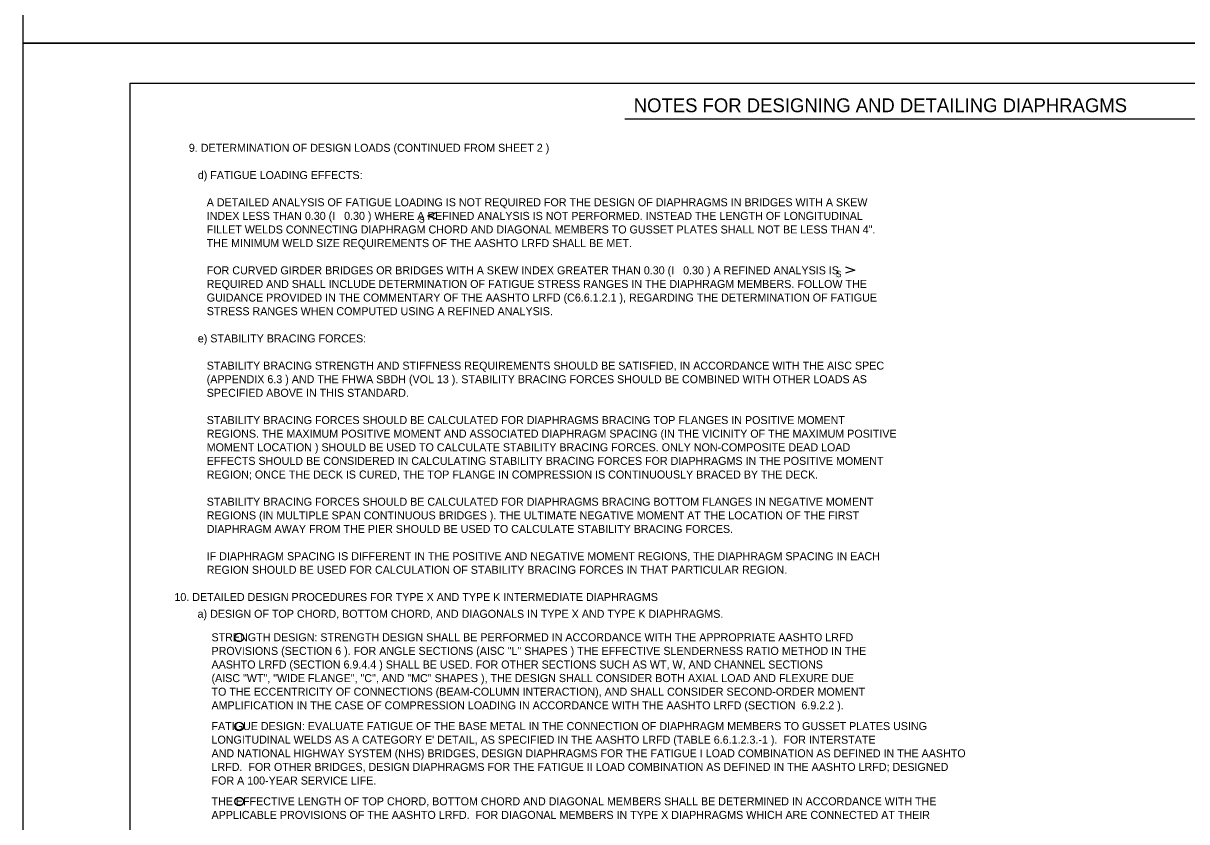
# Model space of a CAD drawing. Extents: x 634656 to 641360, y 298715 to 301183.
# Drawn here: x 637375.4 to 637811.5, y 299027.4 to 299326.5 of the extents above; entities that cross this region are included whole.
import ezdxf

# ---------------------------------------------------------------- set-up
doc = ezdxf.new("R2010")
doc.units = 0
for name, color, linetype in [('1', 7, 'Continuous'), ('2', 7, 'Continuous'), ('PLT-BNDY', 7, 'Continuous')]:
    doc.layers.add(name, color=color, linetype=linetype)

msp = doc.modelspace()

# ---------------------------------------------------------------- linework, layer by layer
at = {"layer": '1'}
for points in [[(637530.45, 299255.59), (637526.91, 299254.41), (637530.45, 299253.23)], [(637683.57, 299235.19), (637687.11, 299234.01), (637683.57, 299232.83)]]:
    msp.add_lwpolyline(points, dxfattribs=at)
for centre in [(637456.32, 299096.41), (637456.32, 299063.06), (637456.32, 299034.89)]:
    msp.add_circle(centre, 1.61, dxfattribs=at)
at = {"layer": '2'}
for p, q in [((637415.43, 298739.99), (637415.43, 299303.99)), ((637415.43, 299303.99), (638201.43, 299303.99)), ((637600.92, 299290.65), (637946.3, 299290.65))]:
    msp.add_line(p, q, dxfattribs=at)
at = {"layer": 'PLT-BNDY'}
for points in [[(637375.43, 299912.99), (638216.43, 299912.99), (638216.43, 299318.99), (637375.43, 299318.99)], [(637375.43, 299318.99), (638216.43, 299318.99), (638216.43, 298724.99), (637375.43, 298724.99)]]:
    msp.add_lwpolyline(points, close=True, dxfattribs=at)

# ---------------------------------------------------------------- texts
at = {"layer": '1'}
for s, height, p in [('NOTES FOR DESIGNING AND DETAILING DIAPHRAGMS ', 5.1838, (637604.21, 299293.18)), ('9. DETERMINATION OF DESIGN LOADS (CONTINUED FROM SHEET 2 )', 2.9999, (637437.49, 299278.33)), ('   d) FATIGUE LOADING EFFECTS:', 2.9999, (637437.49, 299268.13)), ('      A DETAILED ANALYSIS OF FATIGUE LOADING IS NOT REQUIRED FOR THE DESIGN OF DIAPHRAGMS IN BRIDGES WITH A SKEW', 2.99987, (637437.49, 299257.93)), ('      INDEX LESS THAN 0.30 (I   0.30 ) WHERE A REFINED ANALYSIS IS NOT PERFORMED. INSTEAD THE LENGTH OF LONGITUDINAL', 2.99987, (637437.49, 299252.83)), ('      FILLET WELDS CONNECTING DIAPHRAGM CHORD AND DIAGONAL MEMBERS TO GUSSET PLATES SHALL NOT BE LESS THAN 4".', 2.99987, (637437.49, 299247.73)), ('S', 2.4, (637523.72, 299251.78)), ('      THE MINIMUM WELD SIZE REQUIREMENTS OF THE AASHTO LRFD SHALL BE MET.', 2.9999, (637437.49, 299242.63)), ('      FOR CURVED GIRDER BRIDGES OR BRIDGES WITH A SKEW INDEX GREATER THAN 0.30 (I   0.30 ) A REFINED ANALYSIS IS', 2.99987, (637437.49, 299232.43)), ('S', 2.4, (637679.92, 299231.38)), ('      REQUIRED AND SHALL INCLUDE DETERMINATION OF FATIGUE STRESS RANGES IN THE DIAPHRAGM MEMBERS. FOLLOW THE', 2.99987, (637437.49, 299227.33)), ('      GUIDANCE PROVIDED IN THE COMMENTARY OF THE AASHTO LRFD (C6.6.1.2.1 ), REGARDING THE DETERMINATION OF FATIGUE', 2.99987, (637437.49, 299222.23)), ('      STRESS RANGES WHEN COMPUTED USING A REFINED ANALYSIS.', 2.9999, (637437.49, 299217.13)), ('   e) STABILITY BRACING FORCES:', 2.9999, (637437.49, 299206.93)), ('      STABILITY BRACING STRENGTH AND STIFFNESS REQUIREMENTS SHOULD BE SATISFIED, IN ACCORDANCE WITH THE AISC SPEC', 2.99987, (637437.49, 299196.73)), ('      (APPENDIX 6.3 ) AND THE FHWA SBDH (VOL 13 ). STABILITY BRACING FORCES SHOULD BE COMBINED WITH OTHER LOADS AS', 2.99987, (637437.49, 299191.64)), ('      SPECIFIED ABOVE IN THIS STANDARD.', 2.9999, (637437.49, 299186.54)), ('      STABILITY BRACING FORCES SHOULD BE CALCULATED FOR DIAPHRAGMS BRACING TOP FLANGES IN POSITIVE MOMENT', 2.99987, (637437.49, 299176.34)), ('      REGIONS. THE MAXIMUM POSITIVE MOMENT AND ASSOCIATED DIAPHRAGM SPACING (IN THE VICINITY OF THE MAXIMUM POSITIVE', 2.99987, (637437.49, 299171.24)), ('      MOMENT LOCATION ) SHOULD BE USED TO CALCULATE STABILITY BRACING FORCES. ONLY NON-COMPOSITE DEAD LOAD', 2.99987, (637437.49, 299166.14)), ('      EFFECTS SHOULD BE CONSIDERED IN CALCULATING STABILITY BRACING FORCES FOR DIAPHRAGMS IN THE POSITIVE MOMENT', 2.99987, (637437.49, 299161.04)), ('      REGION; ONCE THE DECK IS CURED, THE TOP FLANGE IN COMPRESSION IS CONTINUOUSLY BRACED BY THE DECK.', 2.99987, (637437.49, 299155.94)), ('      STABILITY BRACING FORCES SHOULD BE CALCULATED FOR DIAPHRAGMS BRACING BOTTOM FLANGES IN NEGATIVE MOMENT', 2.99987, (637437.49, 299145.74)), ('      REGIONS (IN MULTIPLE SPAN CONTINUOUS BRIDGES ). THE ULTIMATE NEGATIVE MOMENT AT THE LOCATION OF THE FIRST', 2.99987, (637437.49, 299140.64)), ('      DIAPHRAGM AWAY FROM THE PIER SHOULD BE USED TO CALCULATE STABILITY BRACING FORCES.', 2.9999, (637437.49, 299135.54)), ('      IF DIAPHRAGM SPACING IS DIFFERENT IN THE POSITIVE AND NEGATIVE MOMENT REGIONS, THE DIAPHRAGM SPACING IN EACH', 2.99987, (637437.49, 299125.34)), ('      REGION SHOULD BE USED FOR CALCULATION OF STABILITY BRACING FORCES IN THAT PARTICULAR REGION.', 2.9999, (637437.49, 299120.24)), ('10. DETAILED DESIGN PROCEDURES FOR TYPE X AND TYPE K INTERMEDIATE DIAPHRAGMS', 2.9999, (637432.07, 299110.04)), ('   a) DESIGN OF TOP CHORD, BOTTOM CHORD, AND DIAGONALS IN TYPE X AND TYPE K DIAPHRAGMS. ', 2.9999, (637437.42, 299103.75)), ('        STRENGTH DESIGN: STRENGTH DESIGN SHALL BE PERFORMED IN ACCORDANCE WITH THE APPROPRIATE AASHTO LRFD', 2.99987, (637437.06, 299094.96)), ('        PROVISIONS (SECTION 6 ). FOR ANGLE SECTIONS (AISC "L" SHAPES ) THE EFFECTIVE SLENDERNESS RATIO METHOD IN THE', 2.99987, (637437.06, 299089.86)), ('        AASHTO LRFD (SECTION 6.9.4.4 ) SHALL BE USED. FOR OTHER SECTIONS SUCH AS WT, W, AND CHANNEL SECTIONS ', 2.99987, (637437.06, 299084.76)), ('        (AISC "WT", "WIDE FLANGE", "C", AND "MC" SHAPES ), THE DESIGN SHALL CONSIDER BOTH AXIAL LOAD AND FLEXURE DUE ', 2.99987, (637437.06, 299079.67)), ('        TO THE ECCENTRICITY OF CONNECTIONS (BEAM-COLUMN INTERACTION), AND SHALL CONSIDER SECOND-ORDER MOMENT ', 2.99987, (637437.06, 299074.57)), ('        AMPLIFICATION IN THE CASE OF COMPRESSION LOADING IN ACCORDANCE WITH THE AASHTO LRFD (SECTION  6.9.2.2 ).', 2.99987, (637437.06, 299069.47)), ('        FATIGUE DESIGN: EVALUATE FATIGUE OF THE BASE METAL IN THE CONNECTION OF DIAPHRAGM MEMBERS TO GUSSET PLATES USING', 2.99987, (637437.06, 299061.69)), ("        LONGITUDINAL WELDS AS A CATEGORY E' DETAIL, AS SPECIFIED IN THE AASHTO LRFD (TABLE 6.6.1.2.3.-1 ).  FOR INTERSTATE", 2.99987, (637437.06, 299056.59)), ('        AND NATIONAL HIGHWAY SYSTEM (NHS) BRIDGES, DESIGN DIAPHRAGMS FOR THE FATIGUE I LOAD COMBINATION AS DEFINED IN THE AASHTO', 2.99987, (637437.06, 299051.49)), ('        LRFD.  FOR OTHER BRIDGES, DESIGN DIAPHRAGMS FOR THE FATIGUE II LOAD COMBINATION AS DEFINED IN THE AASHTO LRFD; DESIGNED', 2.99987, (637437.06, 299046.39)), ('        FOR A 100-YEAR SERVICE LIFE.', 2.9999, (637437.06, 299041.29)), ('        THE EFFECTIVE LENGTH OF TOP CHORD, BOTTOM CHORD AND DIAGONAL MEMBERS SHALL BE DETERMINED IN ACCORDANCE WITH THE', 2.99987, (637437.06, 299033.51)), ('        APPLICABLE PROVISIONS OF THE AASHTO LRFD.  FOR DIAGONAL MEMBERS IN TYPE X DIAPHRAGMS WHICH ARE CONNECTED AT THEIR', 2.99987, (637437.06, 299028.41))]:
    msp.add_text(s, height=height, dxfattribs=at).set_placement(p)

doc.saveas('drawing.dxf')
